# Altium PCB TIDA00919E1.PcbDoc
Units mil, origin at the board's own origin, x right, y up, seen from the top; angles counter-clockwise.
Board outline 2372.12 x 2864.32 mil, 2 copper layers (Top Layer, Bottom Layer), stack 62 mil thick; 37 components, 22 nets, 86 pads, 4 vias.
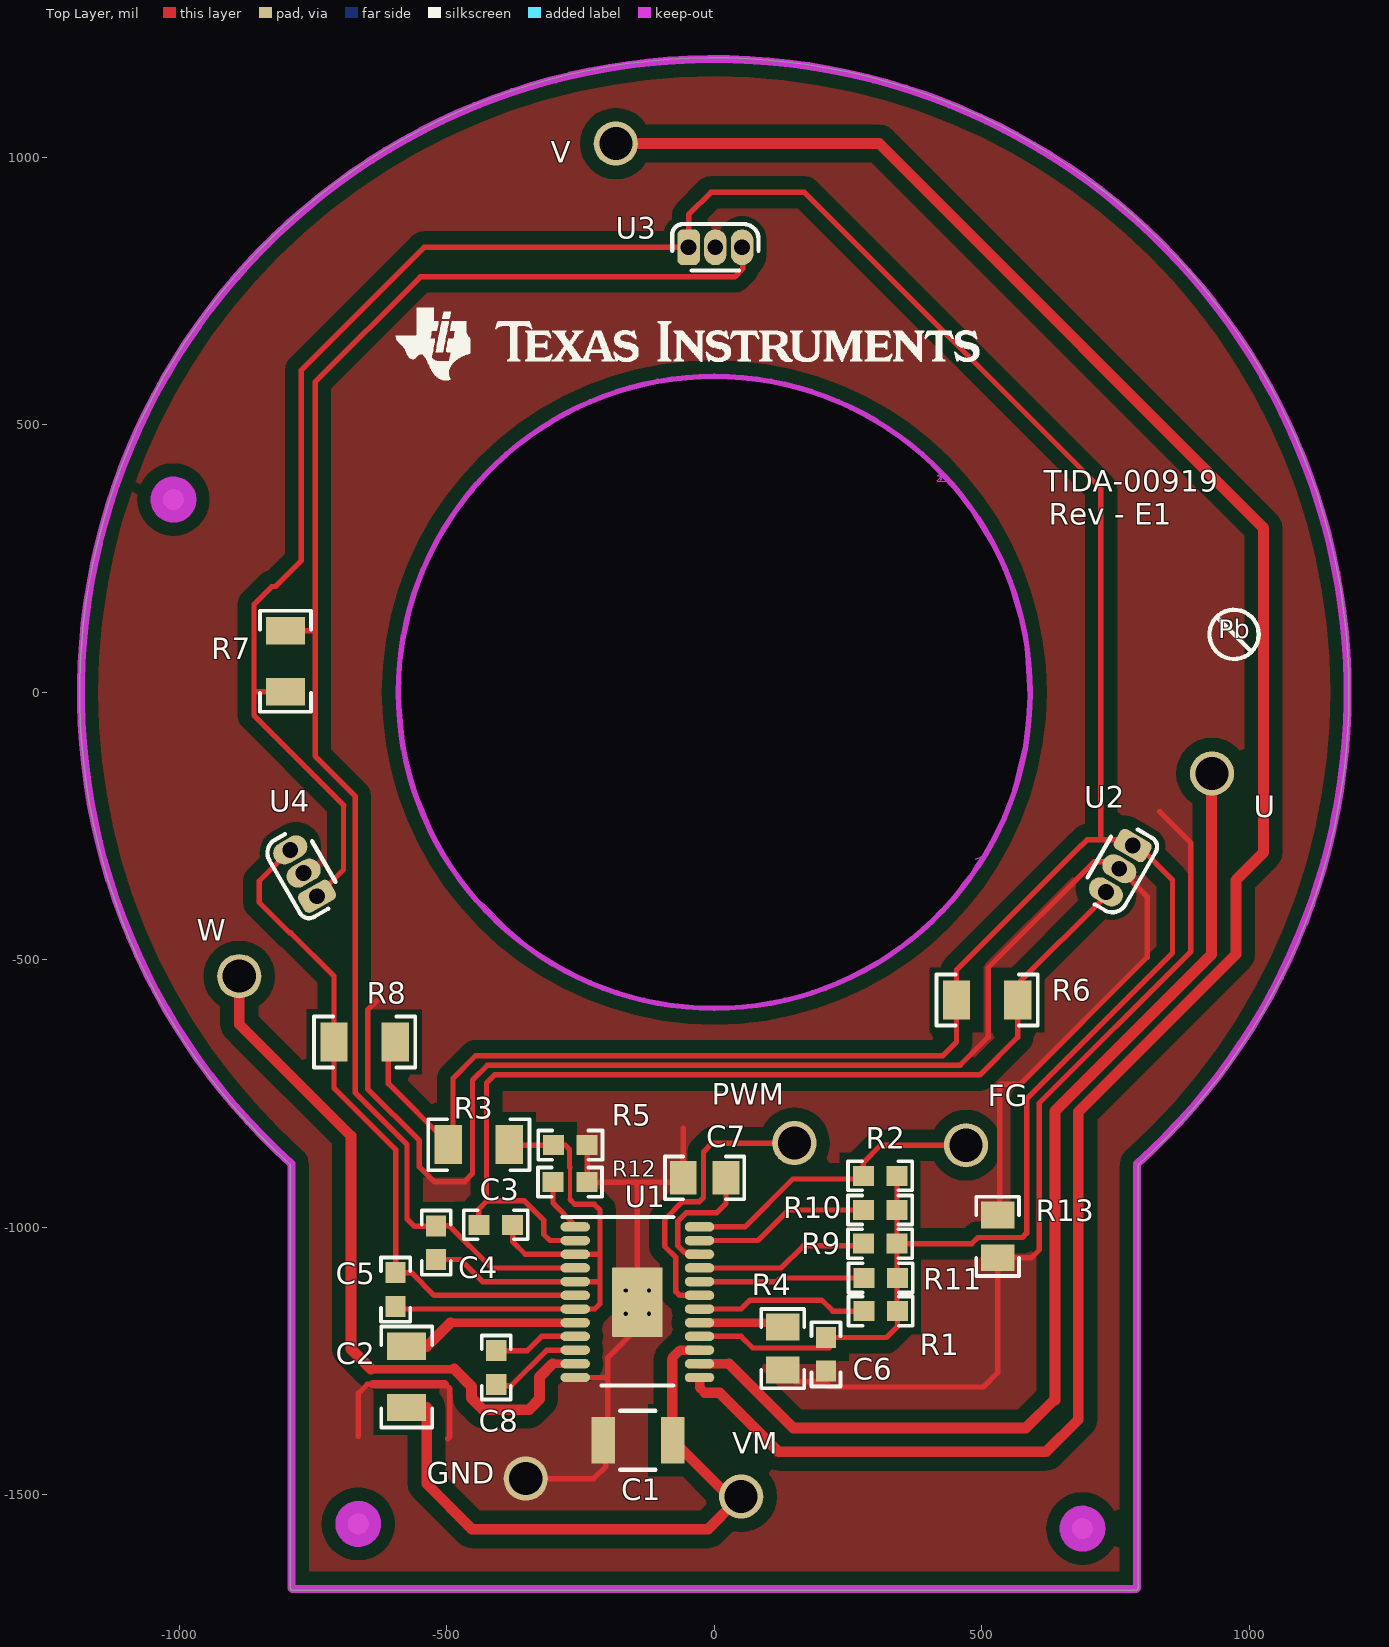
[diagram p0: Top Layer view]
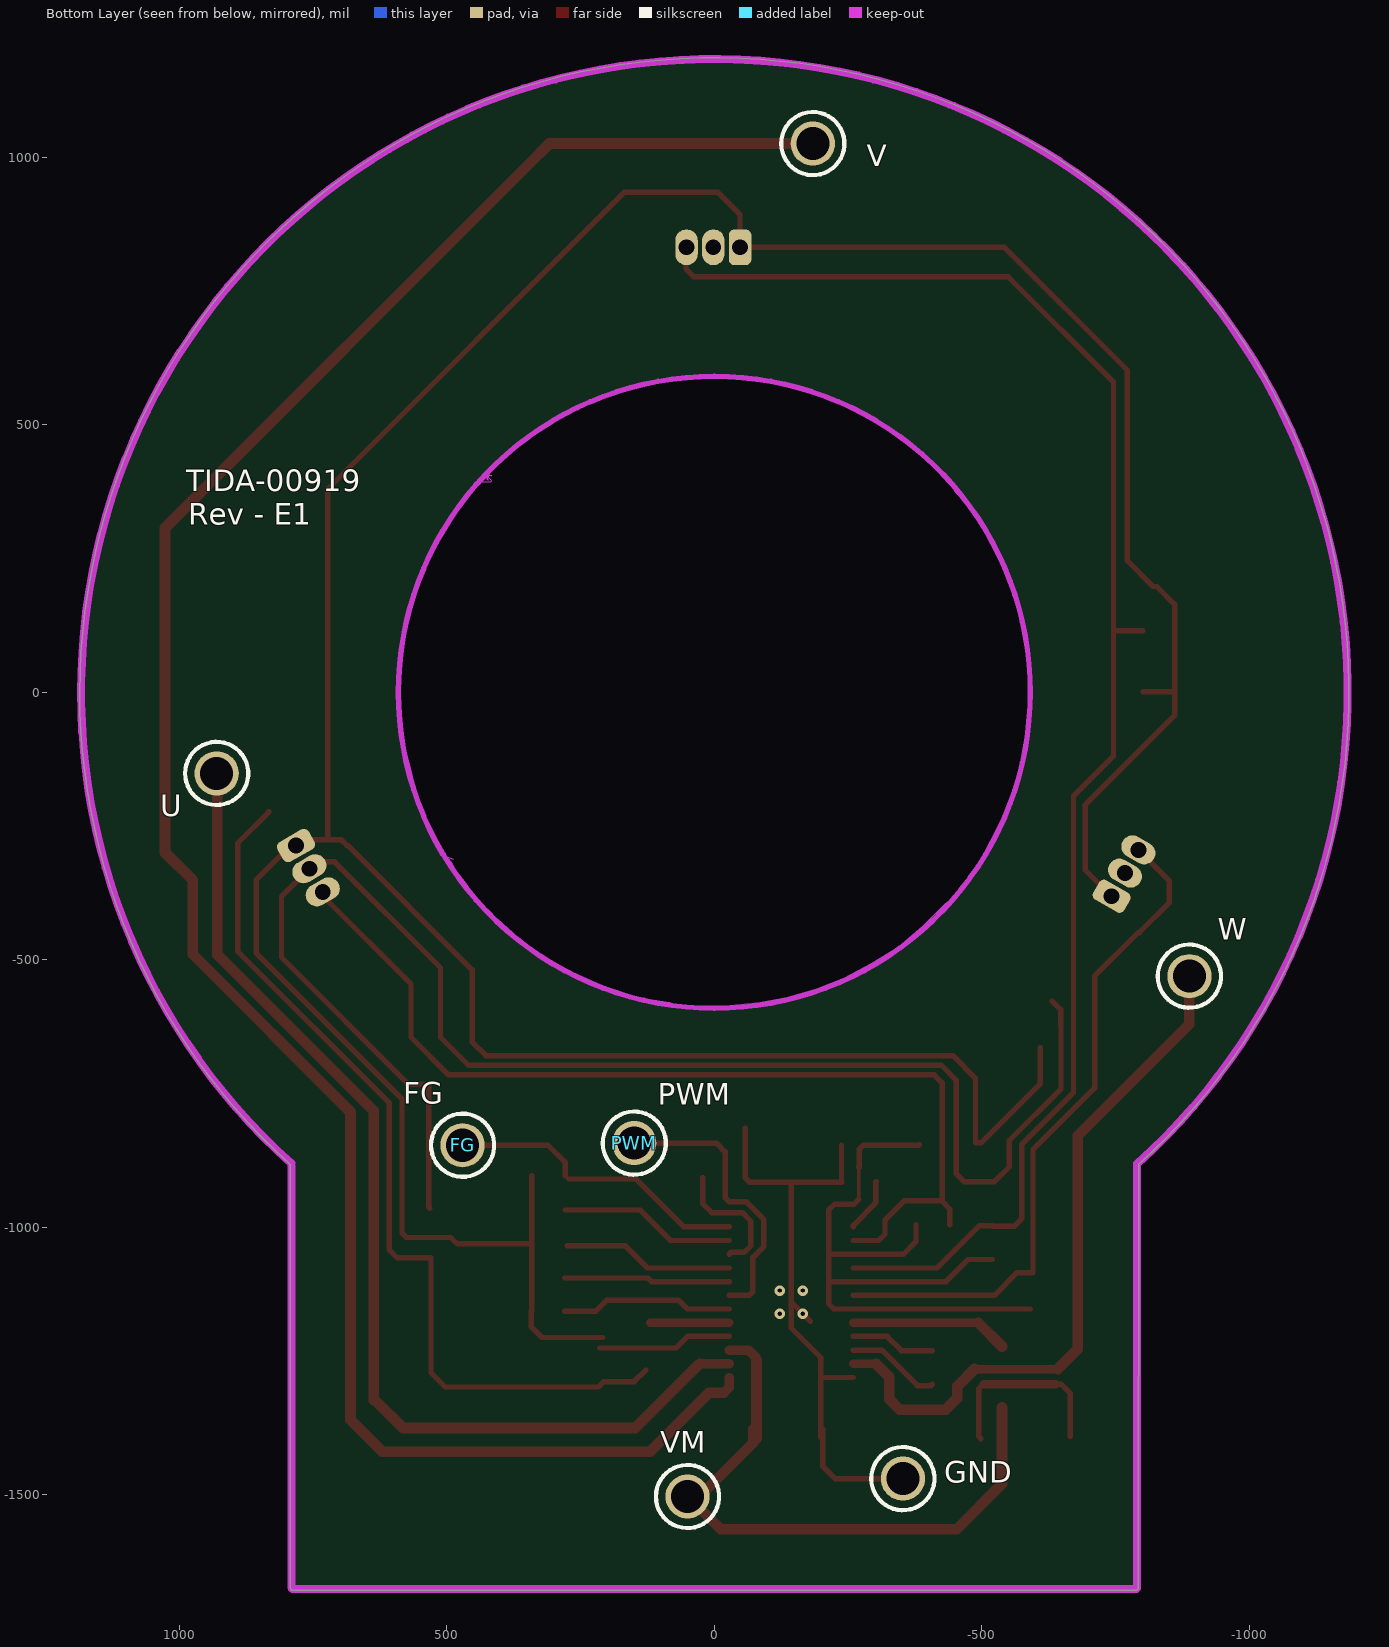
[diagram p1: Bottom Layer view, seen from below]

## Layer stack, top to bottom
Top Solder: solder mask 0.4, Solder Resist, Dk 3.5
Top Layer: signal copper 1.4
Dielectric1: core 59.2, FR-4, Dk 4.8
Bottom Layer: signal copper 1.4
Bottom Solder: solder mask 0.4, Solder Resist, Dk 3.5

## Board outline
-787.4,-1678.24 cw(c-787.4,-1673.23) -792.42,-1673.2 -792.7,-882.32 cw(c0,0) 1186.12,0 cw(c0,0) 793.67,-881.46 cw(c790.31,-877.73) 792.63,-882.18 792.42,-1673.23 ccw(c787.4,-1673.23) 792.42,-1673.23 cw(c787.4,-1673.23) 787.4,-1678.24
cut-out: 416.34,404.53 424.78,404.53 434.11,395.2 434.11,394.01 418,394.01 416.34,395.67 421.85,401.18 421.85,407.51
cut-out: -436.62,396.36 -451.1,373.34 -471.25,353.19 -487.33,327.93 -515.88,280.69 -544.87,227.97 -562.01,174.21 -573.92,119.3 -585.87,64.24 -588.58,3.94 -576.47,-123.77 -556.28,-188.69 -515.88,-285.26 -475.52,-345.3 -446.62,-383.83 -430.29,-396.48 -388.44,-438.33 -344.12,-476.69 -293.44,-507.7 -243.11,-533.99 -216.54,-544.29 -190.12,-554.53 -135.73,-570.87 -84.65,-580.39 -19.68,-586.61 38.39,-585.63 70.87,-583.49 83.36,-580.39 120.14,-574.76 153.68,-566.74 209.65,-548.23 273.62,-519.68 361.21,-467.56 432.76,-397.77 442.13,-388.63 466.41,-354.15 480.78,-336.32 488.06,-323.4 489.12,-321.52 499.74,-307.53 488.06,-311.83 499.06,-307.78 505.04,-299.29 518.37,-280.36 536.89,-236.79 555.12,-193.9 566.82,-146.01 578.2,-99.41 584.34,-51.58 586.61,-6.89 584.34,43.1 581.72,71.85 578.2,110.39 566.93,148.54 546.54,217.6 528.08,259.19 475.71,344.99 443.19,385.34 425.03,402.67 423.4,401.84 424.08,397 423.28,401.78 426.46,402.85 422.3,396.62 423.28,397.64 423.28,398.62 424.08,397.64 425.53,402.45 418.18,412.58 384.15,443.65 372.9,454.9 312.86,497.22 282.5,516.14 240.09,537.61 173.1,562.66 92.39,580.88 8.73,587.77 -55.02,587.77 -118.73,574.49 -135.73,570.94 -168.63,562.66 -208.15,549.34 -228.36,541.57 -252.1,529.7 -267.68,522.52 -282.61,513.96 -307.48,499.69 -328.87,486.4 -381.51,448.11 -434.84,395.94

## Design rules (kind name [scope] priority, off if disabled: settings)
AcuteAngle [All] p1: minimum=4.50000000000000E+0001 checktracksonly=FALSE
AssemblyTestPointUsage [All] p1: valid=2
Clearance Clearance_Keepouts [((IsTrack Or IsArc) And Not InPoly) And IsFree and IsKeepOut vs ((IsTrack Or IsArc) And Not InPoly) And IsFree and IsKeepOut] p1: gap=0
Clearance Clearance_BoardEdge_MountingHoles [OnCopper and InComponentClass('Mounting Holes') vs IsKeepOut] p2: gap=40
Clearance Clearance_BoardEdge_Poly [OnCopper and InPoly vs IsKeepOut] p3: gap=25
Clearance Clearance_BoardEdge [OnCopper and Not InComponentClass('Logo') and not InComponentClass('FiducialMark') and not InRegion(1000,500,4000,800) and Not IsKeepout vs IsKeepOut] p4: gap=75
Clearance Clearance_Poly [InPolygon] p5: gap=25
Clearance [All] p6: gap=7.87
ComponentClearance ComponentClearance_MountingHoles_FiducialMarks [InComponentClass('Mounting Holes') vs InComponentClass('FiducialMark')] p1: gap=50 collisioncheckmode=3 verticalgap=10 showdistances=FALSE
ComponentClearance ComponentClearance_Shunt [InComponentClass('Header') vs InComponentClass('Shunt')] p2: gap=0 collisioncheckmode=3 verticalgap=0 showdistances=FALSE
ComponentClearance ComponentClearance_Logo [InComponentClass('Logo')] p3: gap=50 collisioncheckmode=3 verticalgap=10 showdistances=FALSE
ComponentClearance ComponentClearance_ScrewToNut [(HasFootprint('NY PMS 440 0025 PH')) vs (HasFootprint('Keystone_1902C'))] p4: gap=5 collisioncheckmode=3 verticalgap=10 showdistances=FALSE
ComponentClearance ComponentClearance_MountingHoles [InComponentClass('Mounting Holes')] p5: gap=250 collisioncheckmode=3 verticalgap=100000 showdistances=FALSE
ComponentClearance ComponentClearance_SmallPassives [HasFootprint('0201*') or HasFootprint('0402*') or HasFootprint('0508') or HasFootprint('0603*') or HasFootprint('0612') or HasFootprint('0805*') or HasFootprint('0815*') or HasFootprint('0830*') or HasFootprint('1206*') or HasFootprint('1210*') or HasFootprint('1808*') or HasFootprint('1812*') or HasFootprint('1825*') or HasFootprint('2010*') or HasFootprint('2220*') or HasFootprint('2225*') or HasFootprint('2512*') or HasFootprint('2728*') or HasFootprint('3518*') vs HasFootprint('0201*') or HasFootprint('0402*') or HasFootprint('0508') or HasFootprint('0603*') or HasFootprint('0612') or HasFootprint('0805*') or HasFootprint('0815*') or HasFootprint('0830*') or HasFootprint('1206*') or HasFootprint('1210*') or HasFootprint('1808*') or HasFootprint('1812*') or HasFootprint('1825*') or HasFootprint('2010*') or HasFootprint('2220*') or HasFootprint('2225*') or HasFootprint('2512*') or HasFootprint('2728*') or HasFootprint('3518*')] p6: gap=20 collisioncheckmode=3 verticalgap=10 showdistances=FALSE
ComponentClearance ComponentClearance_THtoSMT [IsThruComponent vs IsSMTComponent] p7: gap=100 collisioncheckmode=3 verticalgap=30 showdistances=FALSE
ComponentClearance ComponentClearance_THtoTH [IsThruComponent vs IsThruComponent] p8: gap=118.11 collisioncheckmode=3 verticalgap=30 showdistances=FALSE
ComponentClearance [All] p9: gap=40 collisioncheckmode=3 verticalgap=10 showdistances=FALSE
DiffPairsRouting [All] p1: maxlimit=100 minlimit=10 mostfreqgap=10 toplayer_minwidth=15 toplayer_maxwidth=15 toplayer_prefwidth=15 bottomlayer_minwidth=15 bottomlayer_maxwidth=15 bottomlayer_prefwidth=15 maxuncoupledlength=1000
FabricationTestPointUsage TestPointUsage [All] p1: valid=2 allowmultiple=FALSE
FabricationTestpoint Testpoint [All] p1: side=3 testpointundercomponent=TRUE minsize=40 maxsize=100 preferedsize=60 minholesize=0 maxholesize=40 preferedholesize=32 testpointgrid=1 allowsidetop=TRUE allowsidebottom=TRUE usegrid=TRUE gridtolerance=0.01
FanoutControl Fanout_LCC [IsLCC] p1: bgadir=Out bgaviamode=Centered fanoutstyle=Auto fanoutdirection=Alternating viagrid=1 // Fanout_LCC (Default Rule)
FanoutControl Fanout_BGA [IsBGA] p2: bgadir=Out bgaviamode=Centered fanoutstyle=Auto fanoutdirection=Alternating viagrid=1 // Fanout_BGA (Default Rule)
FanoutControl Fanout_Default [All] p4: bgadir=Out bgaviamode=Centered fanoutstyle=Auto fanoutdirection=Alternating viagrid=1 // Fanout_Default (Default Rule)
FanoutControl Fanout_Small [(CompPinCount < 5)] p5: bgadir=Out bgaviamode=Centered fanoutstyle=Auto fanoutdirection=OutThenIn viagrid=1 // Fanout_Small (Default Rule)
HoleSize [All] p1: absolutevalues=TRUE maxlimit=251 minlimit=7 maxpercent=80.000 minpercent=20.000
MinimumAnnularRing MinimumAnnularRing_ThermalPadVias [IsVia and InAnyComponent] p1: minimumring=5.91
MinimumAnnularRing [All] p2: minimumring=5
MinimumSolderMaskSliver MinimumSolderMaskSliver_Logo [InComponentClass('Logo') vs InComponentClass('Logo')] p1: minsoldermaskwidth=0.7
MinimumSolderMaskSliver [All] p2: minsoldermaskwidth=3.93
PlaneConnect [All] p1: planeconnectstyle=Relief reliefexpansion=10 reliefentries=4 reliefconductorwidth=10 reliefairgap=10
PolygonConnect [All] p1: connectstyle=Direct reliefconductorwidth=10 reliefentries=4 polygonreliefangle="90 Angle" airgapwidth=10
RoutingVias ThermalPadVias [IsVia and InAnyComponent] p1: holewidth=7.87 width=19.68 viastyle="Through Hole" minholewidth=7.87 minwidth=19.68 maxholewidth=12.99 maxwidth=23.62
RoutingVias [All] p2: holewidth=16 width=34 viastyle="Through Hole" minholewidth=7.87 minwidth=26 maxholewidth=40 maxwidth=65
SilkToBoardRegionClearance [Not ((IsComment or IsDesignator) And (Hide <> 'False')) and not InRegion(1000,500,4000,800)] p1:
SilkToSilkClearance SilkToSilkClearance_Pb-FreeLogo [(HasFootprint('Pb-Free_Overlay_Medium') OR HasFootprint('Pb-Free_Overlay_Small')) vs (HasFootprint('Pb-Free_Overlay_Medium') OR HasFootprint('Pb-Free_Overlay_Small'))] p1: silktosilkclearance=0
SilkToSilkClearance [All] p2: silktosilkclearance=4
SilkToSolderMaskClearance SilkToComonentPadClearance [IsPad and InAnycomponent] p1: minsilkscreentomaskgap=5 clearancetoexposedcopper=TRUE
SilkToSolderMaskClearance "Silk to Solder Mask Opening" [All] p2: minsilkscreentomaskgap=4 clearancetoexposedcopper=FALSE
SolderMaskExpansion [All] p1: expansion=1.97
Width [All] p1: maxlimit=100 minlimit=6 preferedwidth=10 checkconnectedcopper=TRUE
15 further rules are at their usual default settings.

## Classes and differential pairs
component class TIDA_00919: C1 C2 C3 C4 C5 C6 C7 C8 FG GND PWM R1 R2 R3 R4 R5 R6 R7 R8 R9 R10 R11 R12 R13 U U1 U2 U3 U4 V VM W
component class TID_Hardware: Logo2

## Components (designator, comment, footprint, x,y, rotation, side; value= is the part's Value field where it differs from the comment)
1 "Fiducial" Fiducial10-20 687.99,-1562.99 r0 top
2 "Fiducial" Fiducial10-20 -665.35,-1554.13 r0 top
3 "Fiducial" Fiducial10-20 -1010.83,360.24 r0 top
4 "Texas Instruments" TI_Horizontal_Overlay_Small -50.2,651.57 r0 top
5 "Pb-Free Symbol" Pb-Free_Overlay_Small 971.46,108.27 r0 top
C1 "C3225X7R1H106M250AC" 1210_280 -142.72,-1397.64 r180 top
C2 "C3216X7R1E105K085AA" 1206 -574.8,-1279.53 r270 top
C3 "C0603C104M4RACTU" 0603 -408.46,-995.08 r180 top
C4 "C0603C104M4RACTU" 0603 -519.68,-1028.54 r90 top
C5 "C0603C104M4RACTU" 0603 -595.47,-1116.14 r90 top
C6 "C0603C225K8PACTU" 0603 208.66,-1237.2 r270 top
C7 "CC0805KRX7R8BB104" 0805_HV -18.07,-907.48 r180 top
C8 "06033C104KAT2A" 0603 -407.48,-1261.81 r270 top
FG "TESTPOINT" Keystone_1402-3 470.47,-846.46 r90 bottom
GND "TESTPOINT" Keystone_1402-3 -352.36,-1469.49 r180 bottom
PWM "TESTPOINT" Keystone_1402-3 149.65,-842.48 r90 bottom
R1 "CRCW060310K0JNEA" 0603 311,-1156.52 r0 top
R2 "CRCW060310K0JNEA" 0603 310.04,-903.52 r0 top
R3 "CRCW120610K0JNEA" 1206 -439.96,-845.47 r180 top
R4 "RT0805BRD0724KL" 0805_HV 127.95,-1226.38 r90 top
R5 "CRCW060310K0JNEA" 0603 -268.99,-846.16 r180 top
R6 "CRCW120610K0JNEA" 1206 509.84,-574.8 r180 top
R7 "CRCW120610K0JNEA" 1206 -801.18,58.07 r270 top
R8 "CRCW120610K0JNEA" 1206 -653.54,-653.54 r0 top
R9 "CRCW060310K0JNEA" 0603 310.04,-1030.51 r0 top
R10 "CRCW060310K0JNEA" 0603 310.04,-967.5 r0 top
R11 "CRCW060310K0JNEA" 0603 311.02,-1094.49 r0 top
R12 "CRCW060310K0JNEA" 0603 -269.69,-915.35 r180 top
R13 "CRCW08050000Z0EA" 0805_HV 529.53,-1016.73 r270 top
U "TESTPOINT" Keystone_1402-3 930.12,-151.57 r180 bottom
U1 "DRV10970PWP" PWP0024D_N -143.7,-1139.76 r0 top
U2 "DRV5013ADQLPGM" LPG0003A 756.89,-329.72 r240 top
U3 "DRV5013ADQLPGM" LPG0003A 1.97,831.69 r0 top
U4 "DRV5013ADQLPGM" LPG0003A -767.46,-337.9 r120 top
V "TESTPOINT" Keystone_1402-3 -184.06,1025.59 r180 bottom
VM "TESTPOINT" Keystone_1402-3 50.2,-1502.95 r180 bottom
W "TESTPOINT" Keystone_1402-3 -887.8,-530.51 r180 bottom

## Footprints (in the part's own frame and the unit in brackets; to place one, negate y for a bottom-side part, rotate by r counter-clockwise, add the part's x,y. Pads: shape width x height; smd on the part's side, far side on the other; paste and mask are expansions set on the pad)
0603 [mm] "0603 from SM-752 data"
  rect 1x0.95 smd: 1(-0.8,0) 2(0.8,0)
  silkscreen extent -1.52,-0.69 1.52,0.69, body extent -0.87,-0.47 0.87,0.47, height 1
0805_HV [mil] "0805 with 30mil clearance between pads"
  rect 50x63 smd: 1(-40,0) 2(40,0)
  silkscreen extent -74,-40 74,40, body extent -43,-29 43,29, height 57
1206 [mm] "1206 from SM-752 data"
  rect 1.3x1.85 smd: 1(-1.45,0) 2(1.45,0)
  silkscreen extent -2.4,-1.21 2.4,1.21, body extent -1.7,-0.9 1.7,0.9, height 1.35
1210_280 [mm] "SMD, 2-Leads, Body 3.6x2.8mm, Height 2.8mm"
  rect 1.1x2.2 smd: 1(-1.65,0) 2(1.65,0)
  silkscreen extent -0.84,-1.4 0.84,1.4, body extent -1.8,-1.4 1.8,1.4, height 2.8
Fiducial10-20 [mm]
  round 1 smd mask+0.5: 1(0,0)
  Top Layer keep-out circle w1.178: c0,0 r0.5
Keystone_1402-3 [mm] "Micro Pin, Swage Mount"
  round 2.1 hole 1.57: 1(0,0)
  silkscreen extent -1.5,-1.5 1.5,1.5, body extent -1.18,-1.18 1.18,1.18, height 7.01
LPG0003A [mm] "TO, Flat Index; 3 In-Line, Axial Leads Texas Instruments Recommended"
  rrect50% 1.07x1.7 hole 0.75: 1(-1.27,0)
  oval 1.07x1.7 hole 0.75: 2(0,0) 3(1.27,0)
  silkscreen extent -2.05,-1.1 2.05,1.1, body extent -2,-0.98 2,0.54, height 5.06
Pb-Free_Overlay_Small [mil]
  silkscreen extent -46,-46 46,46
PWP0024D_N [mm] "SOP, 24-Leads, Body 7.8x4.4mm, Pitch 0.65mm, Thermal Pad 3.3X2.4mm, IPC Medium Density"
  rrect100% 1.4x0.45 smd: 1(-2.95,3.575) 2(-2.95,2.925) 3(-2.95,2.275) 4(-2.95,1.625) 5(-2.95,0.975) 6(-2.95,0.325) 7(-2.95,-0.325) 8(-2.95,-0.975) 9(-2.95,-1.625) 10(-2.95,-2.275) 11(-2.95,-2.925) 12(-2.95,-3.575) 13(2.95,-3.575) 14(2.95,-2.925) 15(2.95,-2.275) 16(2.95,-1.625) 17(2.95,-0.975) 18(2.95,-0.325) 19(2.95,0.325) 20(2.95,0.975) 21(2.95,1.625) 22(2.95,2.275) 23(2.95,2.925) 24(2.95,3.575)
  rrect4% 2.4x3.3 smd: 25(0,0)
  silkscreen extent -3.55,-3.95 1.7,4.05, body extent -3.21,-3.9 3.21,3.9, height 1.2
TI_Horizontal_Overlay_Small [mil]
  silkscreen extent -545,-68 545,67

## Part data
1 2 3: "Fiducial mark.  There is nothing to buy or mount."
4: library part TI_Logo, "Texas Instrument Corporate Signature"
5: library part Pb-Free
C1: "CAP, CERM, 10 µF, 50 V, +/- 20%, X7R, 1210"
C2: "CAP, CERM, 1 µF, 25 V, +/- 10%, X7R, 1206"
C3 C4 C5: "CAP, CERM, 0.1 µF, 16 V, +/- 20%, X7R, 0603"
C6: "CAP, CERM, 2.2 µF, 10 V, +/- 10%, X5R, 0603"
C7: "CAP, CERM, 0.1 µF, 25 V, +/- 10%, X7R, 0805"
C8: "CAP, CERM, 0.1 µF, 25 V, +/- 10%, X7R, 0603"
FG GND PWM U V VM W: library part 1402-3, "Micro Pin, Gold, Swage Mount"
R1 R2 R5 R9 R10 R11 R12: "RES, 10 k, 5%, 0.1 W, 0603"
R3 R6 R7 R8: "RES, 10 k, 5%, 0.25 W, 1206"
R4: "RES, 24.0 k, 0.1%, 0.125 W, 0805"
R13: "RES, 0, 5%, 0.125 W, 0805"
U1: "3-Phase Brushless DC Motor Driver, PWP0024D"
U2 U3 U4: "Digital-Latch Hall Effect Sensor, LPG0003A"

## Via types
v1: diameter 19.68, hole 7.87, Top Layer to Bottom Layer, 4 vias

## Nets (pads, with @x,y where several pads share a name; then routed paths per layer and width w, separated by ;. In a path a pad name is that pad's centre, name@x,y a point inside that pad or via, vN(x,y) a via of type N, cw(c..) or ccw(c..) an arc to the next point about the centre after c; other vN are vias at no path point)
BRKMOD: R9.1 U1.21 | length 319.3
  Top Layer w10: U1.21 125,-1075.79 166.34,-1034.45 R9.1@274.61,-1034.45
CMTMOD: R11.1 U1.20 | length 309.9
  Top Layer w10: U1.20 117.13,-1101.38 124.02,-1094.49 R11.1
CPN: C8.2 U1.10 | length 176.2
  Top Layer w10: C8.2 -404.98,-1295.81 -379.47,-1295.81 -312.99,-1229.33 U1.10
CPP: C8.1 U1.9 | length 158.6
  Top Layer w10: C8.1 -349.41,-1230.31 -322.83,-1203.74 U1.9
CS: R4.2 U1.17 | length 147.3
  Top Layer w16: U1.17 R4.2@119.72,-1178.15
DAA: R12.2 U1.1 | length 102.3
  Top Layer w10: R12.2@-302.46,-914.37 -301.47,-915.35 -301.47,-954.43 -259.84,-996.06 U1.1
FG: FG.1 R2.1 U1.24 | length 567.2
  Top Layer w10: U1.24 57.09,-999.02 146.65,-909.45 R2.1@272.62,-909.45 ; R2.1 278.54,-878.94 311.02,-846.46 FG.1
FR: R10.1 U1.23 | length 329.8
  Top Layer w10: U1.23 81.69,-1024.61 138.8,-967.5 R10.1
GND: C1.2 C6.2 C7.2 GND.1 R4.1 R5.1 R12.1 R13.1 R13.2 U1.12 U1.25 U2.2 U3.2 U4.2 | length 6131.9
  Top Layer w10: -665.35,-1390.75 -665.35,-1310.04 -648.62,-1293.31 -637.8,-1293.31 ; -630.91,-576.77 -647.09,-592.95 -647.6,-592.95 -647.6,-621.44 -647.72,-621.56 -647.72,-741.06 -551.18,-837.6 -551.18,-886.81 -523.62,-914.37 -466.54,-914.37 -451.77,-899.61 -451.77,-724.57 -424.21,-697.01 459.49,-697.01 511.81,-644.69 511.81,-514.76 709.65,-316.93 744.09,-316.93 U2.2 809.06,-381.89 809.06,-495.08 571.38,-732.76 533.46,-732.76 533.46,-962.6 R13.1@531.5,-964.57 ; -503.94,-1293.31 -501.97,-1293.31 -494.09,-1301.18 -494.09,-1390.75 -498.03,-1394.68 ; GND.1 -225.39,-1469.49 -202.76,-1446.85 C1.2@-202.76,-1376.97 ; U1.12 -201.77,-1280.51 -198.82,-1277.56 ; R5.1 -237.5,-914.37 -238.48,-915.35 -145.67,-915.35 ; C1.2@-198.82,-1392.72 -198.82,-1277.56 ; U1.25@-179.13,-1175.2 U1.25 ; -58.07,-814.96 C7.2 -65.95,-915.35 -145.67,-915.35 ; R4.1 149.96,-1288.39 206.69,-1288.39 216.54,-1298.23 502.95,-1298.23 529.53,-1271.65 R13.2 592.87,-1056.73 607.28,-1042.32 607.28,-767.72 890.75,-484.25 890.75,-281.5 832.68,-223.43 ; -198.82,-1277.56 -198.82,-1243.11 -143.7,-1187.99 U1.25 ; -145.67,-915.35 -143.7,-917.32 U1.25
  Top Layer w16: -637.8,-1293.31 -503.94,-1293.31
  other v1: -165.35,-1161.42 -122.05,-1161.42 -165.35,-1118.11 -122.05,-1118.11
PWM: PWM.1 U1.19 | length 546.1
  Top Layer w10: U1.19 -64.96,-1126.97 -71.85,-1120.08 -71.85,-1056.1 -92.52,-1035.43 -92.52,-985.24 -59.14,-951.85 -27.74,-951.85 -20.2,-944.31 -20.2,-858.74 -3.94,-842.48 PWM.1 PWM.1@152.56,-839.57
RD: R1.1 U1.18 | length 322.6
  Top Layer w10: U1.18 50.2,-1152.56 66.93,-1135.83 200.79,-1135.83 221.48,-1156.52 R1.1
RETRY: C7.1 U1.22 | length 244.8
  Top Layer w10: U1.22 -31.42,-1046.34 -56.34,-1046.34 -67.99,-1034.68 -67.99,-988.2 -52.23,-972.44 4.92,-972.44 21.93,-955.43 C7.1
U: U1.14 U.1 | length 2028.5
  Top Layer w10: 634.23,-1322.81 636.81,-1322.81 ; U.1@929.13,-152.56 U.1
  Top Layer w17.72: U1.14 27.56,-1254.92
  Top Layer w20: 27.56,-1254.92 147.64,-1375 582.05,-1375 634.23,-1322.81 ; 636.81,-1322.81 636.81,-782.48 929.13,-490.16 U.1@929.13,-152.56
U_HN: C3.1 C4.1 C5.1 R3.1 R5.2 U1.3 U1.5 U1.7 | length 1359.7
  Top Layer w7: -269.69,-947.83 -269.69,-887.8
  Top Layer w10: C5.1@-590.55,-1152.56 U1.7 -223.43,-1152.56 -213.58,-1142.72 -213.58,-1099.41 ; C4.1 -474.41,-1060.04 -433.07,-1101.38 U1.5 -215.55,-1101.38 -213.58,-1099.41 ; R3.1 -382.18,-846.16 R5.2 -278.54,-846.16 -270.67,-854.04 -270.67,-887.8 -269.69,-887.8 ; C3.1 -376.97,-1026.57 -353.35,-1050.2 U1.3 -213.58,-1050.2 ; -269.69,-947.83 -260.83,-956.69 -224.41,-956.69 -213.58,-967.52 -213.58,-1050.2 ; -213.58,-1099.41 -213.58,-1050.2
U_HP: C3.2 R6.1 U1.2 U2.3 | length 1851.6
  Top Layer w10: C3.2 -439.96,-965.55 -425.2,-950.79 -425.69,-950.3 ; U1.2 -307.09,-1024.61 -318.9,-1012.8 -318.9,-986.22 -354.82,-950.3 -425.69,-950.3 ; U2.3 731.89,-380.32 566.93,-545.28 R6.1 566.93,-644.69 496.73,-714.88 -410.75,-714.88 -425.69,-729.82 -425.69,-950.3
V: U1.13 V.1 | length 4119.1
  Top Layer w17.72: U1.13 -27.56,-1299.21 -17.72,-1309.06
  Top Layer w20: V.1 308.07,1025.59 346.95,986.71 1026.57,307.09 1026.57,-299.21 974.85,-350.94 974.85,-489.72 680.12,-784.45 680.12,-1359.25 620.08,-1419.29 120.08,-1419.29 9.84,-1309.06 -17.72,-1309.06
V_HP: C4.2 R7.1 U1.4 U3.3 | length 2965.5
  Top Layer w10: R7.1 -749.02,115.16 ; U1.4 -415.84,-1075.79 -494.58,-997.05 C4.2 -520.67,-998.03 -560.2,-998.03 -574.31,-983.92 -574.31,-844.98 -671.19,-748.1 -671.19,-193.9 -746.06,-119.02 -746.06,579.72 -549.21,776.57 38.39,776.57 52.96,791.15 U3.3@52.96,829.72
VCP: C2.1 U1.8 | length 295.9
  Top Layer w16: -493.11,-1178.15 U1.8
  Top Layer w20: -537.4,-1222.44 -493.11,-1178.15
VINT: C6.1 R1.2 R2.2 R3.2 R6.2 R7.2 R8.2 R9.2 R10.2 R11.2 U1.16 U2.1 U3.1 U4.1 | length 7418.8
  Top Layer w10: R7.2 -859.25,0.98 -860.24,0 ; U4.1 -692.91,-331.65 -692.91,-212.6 -691.93,-211.61 -860.24,-43.31 -860.24,0 ; R8.2@-609.25,-664.37 -609.25,-731.3 -499.02,-841.54 -488.19,-841.54 -488.19,-721.46 -445.87,-679.13 427.17,-679.13 452.76,-653.54 R6.2 452.76,-518.7 685.03,-286.42 686.02,-286.42 696.85,-275.59 722.44,-275.59 ; U1.16 50.2,-1203.74 71.85,-1225.39 214.57,-1225.39 ; C6.1 321.85,-1205.71 342.5,-1185.06 R1.2 ; R1.2@341.54,-1156.5 R9.2 ; R2.2 R10.2 R9.2 ; -860.24,0 -860.24,164.37 -826.77,197.83 -819.88,197.83 -771.65,246.06 -771.65,602.36 -542.32,831.69 U3.1 -48.03,892.72 -6.44,934.31 168.64,934.31 722.44,380.51 722.44,-275.59 ; R9.2 481.04,-1030.51 492.7,-1018.86 575.63,-1018.86 583.66,-1010.83 583.66,-759.84 856.3,-487.2 856.3,-350.39 792.33,-286.42 U2.1 771.06,-275.59 722.44,-275.59
VM: C1.1 C2.2 U1.15 VM.1 | length 1172.1
  Top Layer w10: -78.74,-1248.03 -78.74,-1244.09 ; C1.1 C1.1@-72.83,-1402.56
  Top Layer w17.72: -78.74,-1244.09 -63.98,-1229.33 U1.15
  Top Layer w20: -537.4,-1336.61 -537.4,-1479.33 -452.76,-1563.98 -11.81,-1563.98 38.39,-1513.78 -72.83,-1402.56 C1.1@-72.83,-1376.97 ; C1.1@-78.74,-1394.68 -78.74,-1248.03
W: U1.11 W.1 | length 1327
  Top Layer w10: W.1@-917.32,-534.45 W.1@-914.37,-531.5 ; -683.07,-824.8 -679.13,-828.74 ; -641.73,-1264.76 -637.8,-1264.76 ; -503.94,-1264.76 -502.96,-1264.76 ; -492.13,-1264.76 -486.22,-1264.76
  Top Layer w16: -637.8,-1264.76 -503.94,-1264.76 -492.13,-1264.76 ; -302.17,-1254.92 U1.11
  Top Layer w20: W.1 -887.8,-620.08 -868.11,-639.76 -683.07,-824.8 ; -679.13,-828.74 -679.13,-1227.36 -641.73,-1264.76 ; -486.22,-1264.76 -453.74,-1297.24 -453.74,-1318.9 -432.09,-1340.55 -346.46,-1340.55 -326.77,-1320.87 -326.77,-1279.53 -302.17,-1254.92
W_HP: C5.2 R8.1 U1.6 U4.3 | length 1273.9
  Top Layer w10: U4.3 -850.39,-352.53 -850.39,-392.72 -793.8,-449.31 -791.83,-449.31 -710.63,-530.51 R8.1 -710.63,-739.62 -595.47,-854.78 C5.2 -565.94,-1084.65 -523.62,-1126.97 U1.6
pads on no net: 1.1 2.1 3.1

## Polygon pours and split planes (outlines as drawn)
GND on Top Layer "GND_L01_P010" (solid, remove dead copper, pour order 10): -1229.8,1260.3 -1225.86,1256.36 1257.41,1256.36 1257.41,-1792.85 -1243.58,-1792.85 -1243.58,1235.69 -1229.8,1249.47

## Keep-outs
Keep-Out Layer:
  circle w10: c0,0 r590.55
  lines w10: 787.4,-885.83 787.4,-1673.23 -787.4,-1673.23 -787.69,-880.08 cw(c0,0) 787.61,-880.15 ; -792.7,-882.32 cw(c0,0) 1186.12,0 ; -792.7,-882.32 cw(c0,0) 1186.12,0 ; -792.7,-882.32 -792.42,-1673.23 ; -792.7,-882.32 -792.42,-1673.23 ; -792.42,-1673.23 ccw(c-787.4,-1673.23) -787.4,-1678.24 ; -792.42,-1673.23 ccw(c-787.4,-1673.23) -787.4,-1678.24 ; -787.4,-1678.24 787.4,-1678.24 ; -787.4,-1678.24 787.4,-1678.24 ; 787.4,-1678.24 ccw(c787.4,-1673.23) 792.42,-1673.23 ; 787.4,-1678.24 ccw(c787.4,-1673.23) 792.42,-1673.23 ; 792.42,-1673.23 792.42,-885.83 792.42,-1673.23 ; 1186.12,0 cw(c0,0) 791.69,-883.23 ccw(c0,0) 1186.12,0 ; 3768.9,-1875.08 ccw(c3768.9,-1870.08) 3773.9,-1870.08 cw(c3768.9,-1870.08) 3768.9,-1875.08
  text ".Layer_Name" at -604.1,-2728.57 h60

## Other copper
Top Layer:
  text ".Layer_Name" at -604.1,-2728.57 h60
Bottom Layer:
  text ".Layer_Name" at -604.1,-2728.57 h60

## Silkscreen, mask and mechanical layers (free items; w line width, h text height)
Top Overlay:
  text "V" at -306.1,990.16 h40
  text "TIDA-00919" at 616.14,375 h40
  text "Rev - E1" at 625,312.99 h40
  text "U" at 1007.87,-233.27 h40
  text "W" at -967.52,-464.57 h40
  text "VM" at 33.46,-1423.23 h40
  text "GND" at -537.4,-1479.33 h40
  text ".Layer_Name" at -604.1,-2728.57 h60
Bottom Overlay:
  text "TIDA-00919" at 987.2,375.98 h40
  text "Rev - E1" at 983.27,312.99 h40
  text "FG" at 581.69,-768.7 h40
  text "PWM" at 105.32,-770.67 h40
  text ".Layer_Name" at -604.1,-2728.57 h60
Top Paste:
  text ".Layer_Name" at -604.1,-2728.57 h60
Bottom Paste:
  text ".Layer_Name" at -604.1,-2728.57 h60
Top Solder:
  text ".Layer_Name" at -604.1,-2728.57 h60
  text ".Layer_Name" at -604.1,-2728.57 h60
Bottom Solder:
  text ".Layer_Name" at -604.1,-2728.57 h60
Drill Guide:
  text ".Layer_Name" at -604.1,-2728.57 h60
M1 Board Outline:
  circle w10: c0,0 r590.55
  lines w10: 787.61,-880.15 787.4,-1673.23 -787.4,-1673.23 -787.69,-880.08 cw(c0,0) 790.31,-877.73
  text ".Layer_Name" at -604.1,-2728.57 h60
M2 Board Dimensions:
  rectangle: -1056.1,-2270.08 -681.1,-2145.08
  rectangle: -1181.1,-2145.08 -1056.1,-2020.08
  lines w7: -1181.1,-2145.08 -181.1,-2145.08 ; -1056.1,-2270.08 -1056.1,-2020.08 ; -931.1,-2270.08 -931.1,-2020.08 ; -681.1,-2270.08 -681.1,-2020.08 ; -431.1,-2270.08 -431.1,-2020.08 ; -1181.1,-2270.08 -1181.1,-2020.08 -181.1,-2020.08 -181.1,-2270.08 -1181.1,-2270.08
  text ".Layer_Name" at -604.1,-2728.57 h60
M3 3D STEP Top:
  text ".Layer_Name" at -604.1,-2728.57 h60
M4 3D STEP Bottom:
  text ".Layer_Name" at -604.1,-2728.57 h60
M5 Assembly Top:
  lines w10: -1473.1,-2800.25 5126.9,-2800.25 ; -1473.1,-2596.91 5128.9,-2596.91 ; -1473.1,-2393.58 -1473.1,-3003.58 2531.9,-3003.58 5128.9,-3003.58 5128.9,-2393.58 -1472.6,-2393.58 -1472.6,-3003.58 102.9,-3003.58 ; 991.9,-3003.58 991.9,-2393.58 ; 2258.9,-2596.91 2258.9,-2393.58 ; 3098.9,-2596.91 3098.9,-2393.58 ; 3720.9,-3010.08 3720.9,-2807.25
  text "COMPONENTS MARKED 'DNP' SHOULD NOT BE POPULATED." at -27.6,-2188.58 h60
  text "ASSEMBLY VARIANT:" at -28.1,-2304.08 h60
  text ".VariantName" at 1007.9,-2304.08 h60
  text "PCB VIEWED FROM TOP SIDE" at -1409.6,-2525.75 h60
  text "BOARD #:" at 1066.9,-2525.75 h60
  text ".PRJ_Number" at 1612.4,-2525.75 h60
  text "REV:" at 2456.9,-2525.75 h60
  text ".PCB_Rev" at 2748.4,-2525.75 h60
  text "SVN REV:" at 3294.9,-2525.75 h60
  text ".VersionControl_RevNumber" at 3800.9,-2525.75 h60
  text "TID #:" at 1066.9,-2729.08 h60
  text ".TID" at 1612.4,-2729.08 h60
  text "PLOT NAME =" at -1409.6,-2934.41 h60
  text ".plot_File_Name" at -604.1,-2934.41 h60
  text "GENERATED    :" at 1068.9,-2934.41 h60
  text ".Print_Date" at 1938.4,-2934.41 h60
  text ".Print_Time" at 2667.4,-2934.41 h60
  text "TEXAS INSTRUMENTS" at 3931.9,-2934.41 h60
M6 Assembly Bottom:
  lines w10: -1473.6,-2597.41 5128.4,-2597.41 ; -1471.6,-2800.75 5128.4,-2800.75 ; -65.6,-3010.58 -65.6,-2807.75 ; 556.4,-2597.41 556.4,-2394.08 ; 1396.4,-2597.41 1396.4,-2394.08 ; 2663.4,-3004.08 2663.4,-2394.08 ; 3552.4,-3004.08 5127.9,-3004.08 5127.9,-2394.08 -1473.6,-2394.08 -1473.6,-3004.08 1123.4,-3004.08 5128.4,-3004.08 5128.4,-2394.08
  text "COMPONENTS MARKED 'DNP' SHOULD NOT BE POPULATED." at 4920.9,-2188.08 h60
  text ".VariantName" at 3876.9,-2304.08 h60
  text "ASSEMBLY VARIANT:" at 4915.9,-2304.08 h60
  text ".VersionControl_RevNumber" at -145.6,-2526.25 h60
  text "SVN REV:" at 360.4,-2526.25 h60
  text ".PCB_Rev" at 906.9,-2526.25 h60
  text "REV:" at 1198.4,-2526.25 h60
  text ".PRJ_Number" at 2042.9,-2526.25 h60
  text "BOARD #:" at 2588.4,-2526.25 h60
  text "PCB VIEWED FROM BOTTOM SIDE" at 5064.9,-2526.25 h60
  text ".TID" at 2042.9,-2729.58 h60
  text "TID #:" at 2588.4,-2729.58 h60
  text "TEXAS INSTRUMENTS" at -276.6,-2934.91 h60
  text ".Print_Time" at 987.9,-2934.91 h60
  text ".Print_Date" at 1716.9,-2934.91 h60
  text "GENERATED    :" at 2586.4,-2934.91 h60
  text ".plot_File_Name" at 4259.4,-2934.91 h60
  text "PLOT NAME =" at 5064.9,-2934.91 h60
M9 Title Sheet:
  drawing of 57 lines, arcs and shapes, not listed
  text "1" at -441.27,6166.42 h70
  text "2" at 2054.4,6166.42 h70
  text "3" at 4543.74,6166.42 h70
  text "4" at 7050.41,6166.42 h70
  text "5" at 9549.4,6166.42 h70
  text "6" at 12054.4,6166.42 h70
  text "A" at -1597.6,5023.42 h70
  text "A" at 13202.4,5023.42 h70
  text "B" at -1597.6,2643.42 h70
  text "B" at 13202.4,2643.42 h70
  text "C" at -1597.6,268.42 h70
  text "C" at 13202.4,268.42 h70
  text "PROJECT TITLE:" at 10162.4,-1592.58 h45
  text ".PRJ_Title" at 10212.4,-1725.91 h70
  text "DESIGNED FOR:" at 10162.4,-1893.58 h45
  text ".PRJ_Customer" at 10212.4,-2033.58 h70
  text "D" at -1597.6,-2101.58 h70
  text "D" at 13202.4,-2101.58 h70
  text "FILE NAME:" at 10162.4,-2193.58 h45
  text ".PCB_File_Name_No_Path" at 10212.4,-2313.58 h70
  text "Texas Instruments (TI) and/or its licensors do not warrant the accuracy or completeness of this specification" at 5192.9,-2475.42 h45
  text "ENGINEER:" at 10162.4,-2483.58 h45
  text "LAYOUT BY:" at 11667.4,-2483.58 h45
  text "or any information contained therein. TI and/or its licensors do not warrant that this design will meet" at 5147.91,-2588.08 h45
  text ".PRJ_Engineer" at 10212.4,-2638.57 h70
  text ".PCB_Layout" at 11717.9,-2638.57 h70
  text "the specifications, will be suitable for your application or fit for any particular purpose, or will operate in" at 5147.91,-2700.75 h45
  text ".Layer_Name" at -604.1,-2728.57 h60
  text "ALTIUM DESIGNER VERSION:" at 11667.4,-2793.58 h45
  text "an implementation. TI and/or its licensors do not warrant that the design is production worthy. You should" at 5147.91,-2813.41 h45
  text "completely validate and test your design implementation to confirm the system functionality for your application." at 5192.9,-2926.08 h45
  text ".print_Scale" at 10212.4,-2926.91 h70
  text ".Application_BuildNumber" at 11717.9,-2926.91 h70
  text "1" at -441.27,-3133.58 h70
  text "2" at 2054.4,-3133.58 h70
  text "3" at 4543.74,-3133.58 h70
  text "4" at 7050.41,-3133.58 h70
  text "5" at 9549.4,-3133.58 h70
  text "6" at 12054.4,-3133.58 h70
M10 Fab Notes:
  drawing of 173 lines, arcs and shapes, not listed
  text "DESIGN INFORMATION" at 11195.92,4330.92 h60
  text "MIN. TRACK WIDTH:" at 10551.36,4150.92 h60
  text "8" at 11647.6,4150.92 h60
  text "MIL" at 11802.36,4150.92 h60
  text "MIN. CLEARANCE:" at 10551.36,4018.92 h60
  text "0.2" at 11587.6,4018.92 h60
  text "mm" at 11802.36,4018.92 h60
  text "MIN. VIA PAD SIZE:" at 10551.36,3886.92 h60
  text "24" at 11617.61,3886.92 h60
  text "MIL" at 11802.36,3886.92 h60
  text "0.05mm (2MIL)" at 11246.36,3745.21 h60
  text "MINIMUM ANNULAR RING" at 10222.13,3740.93 h60
  text "EXTERNAL" at 11954.36,3740.93 h60
  text "PER" at 10422.13,3622.92 h60
  text "IPC-D-275 CLASS 2 LEVEL C" at 10642.13,3622.92 h60
  text "MIL, HOLES" at 12130.36,3510.63 h60
  text "+/-" at 11737.9,3509.92 h60
  text "+/-" at 12591.9,3509.92 h60
  text "REGISTRATION TOLERANCES:" at 10222.13,3504.92 h60
  text "METAL" at 11421.9,3504.92 h60
  text "5" at 11998.1,3504.92 h60
  text "3" at 12831.1,3504.92 h60
  text "MIL" at 12947.36,3504.92 h60
  text "+/-" at 12591.9,3391.92 h60
  text "HOLE SIZE TOLERANCE (UNLESS OTHERWISE SPECIFIED):" at 10222.13,3386.92 h60
  text "3" at 12831.1,3386.92 h60
  text "MIL" at 12947.36,3386.92 h60
  text "MATERIAL:" at 10147.36,3177.46 h60
  text "FR-4 High Tg" at 11133.8,3037.13 h60
  text "FR-408" at 10568.36,3028.56 h60
  text "OTHER" at 12056.36,3028.56 h60
  text "X" at 10978.9,3024.92 h60
  text "62 MIL (1.6mm) +/-10%" at 10888.46,2865.84 h60
  text "THICKNESS:" at 10222.13,2861.56 h60
  text "X" at 10760.29,2861.56 h60
  text "OTHER" at 12173.36,2861.56 h60
  text "TOLERANCE:" at 10222.13,2703.56 h60
  text "X" at 11061.43,2703.56 h60
  text "ANSI IPC-6012 TYPE 3 CLASS 2" at 11248.37,2703.56 h60
  text "OTHER +/-" at 11248.36,2547.56 h60
  text "BOW & TWIST:" at 10222.13,2390.56 h60
  text "X" at 11061.43,2390.56 h60
  text "ANSI IPC-6012 TYPE 3 CLASS 2" at 11248.37,2390.56 h60
  text "OTHER +/-" at 11248.36,2232.05 h60
  text "DRILLING:" at 10147.36,2093.56 h60
  text "REFERENCE:" at 10222.13,1976.56 h60
  text "X" at 10870.36,1976.56 h60
  text "AS SHOWN" at 11057.36,1976.56 h60
  text "X" at 11771.36,1976.56 h60
  text "NC_DRILL FILES" at 11908.36,1976.56 h60
  text "PTH MIN COPPER THICKNESS:" at 10222.13,1818.56 h60
  text "X" at 11572.36,1818.56 h60
  text "1MIL" at 11709.36,1818.56 h60
  text "OTHER" at 12206.36,1818.56 h60
  text "BOARD FINISH:" at 10147.36,1659.56 h60
  text "SILKSCREEN:" at 10302.58,1541.56 h60
  text "X" at 11251.36,1541.56 h60
  text "TOP" at 11377.36,1541.56 h60
  text "X" at 11761.36,1541.56 h60
  text "BOTTOM" at 11888.36,1541.56 h60
  text "SILKSCREEN COLOR:" at 10302.58,1374.56 h60
  text "X" at 11250.32,1374.56 h60
  text "WHITE" at 11377.36,1374.56 h60
  text "OTHER" at 11888.36,1374.56 h60
  text "X" at 11381.32,1215.36 h60
  text "GREEN" at 11508.36,1215.36 h60
  text "OTHER" at 12126.36,1215.36 h60
  text "SOLDER RESIST COLOR:" at 10302.58,1204.56 h60
  text "X" at 11381.32,1045.36 h60
  text "MATTE" at 11508.36,1045.36 h60
  text "SEMI-GLOSS" at 12125.9,1044.73 h60
  text "IMMERSION GOLD (ENIG)" at 11208.36,856.84 h60
  text "ENEPIG" at 12545.9,853.56 h60
  text "SURFACE FINISH:" at 10147.36,852.56 h60
  text "X" at 11021.41,852.56 h60
  text "IMM. TIN/SILVER OR EQUIV" at 10476.9,695.56 h60
  text "OTHER" at 11908.36,695.56 h60
  text "ARRAY/PANEL:" at 10147.36,516.56 h60
  text "CUT AND TRIM PER M1 BOARD OUTLINE" at 11208.36,512.27 h60
  text "N.C. ROUTE" at 11208.36,360.56 h60
  text "X" at 11887.36,360.56 h60
  text "V. SCORE" at 12074.36,360.56 h60
  text "CERTIFICATION:" at 10147.36,223.56 h60
  text "MATERIALS AND WORKMANSHIP FOR ALL PCBS" at 10872.36,223.56 h60
  text "TO MEET OR EXCEED THE REQUIREMENTS OF:" at 10872.36,125.56 h60
  text "X" at 10498.86,-10.94 h60
  text "ANSI IPC-A-600F CLASS ->" at 10637.86,-10.94 h60
  text "X" at 12276.92,-10.94 h60
  text "2" at 12395.86,-10.94 h60
  text "1" at 12080.86,-12.44 h60
  text "3" at 12749.86,-12.44 h60
  text "X" at 11312.92,-170.44 h60
  text "RoHS" at 11449.86,-170.44 h60
  text "OTHER" at 12094.26,-170.44 h60
  text "PER ORDER" at 12491.32,-170.44 h60
  text "ALL BOARDS MUST MEET OR EXCEED UL94-V0 REQUIREMENTS." at 10174.9,-336.08 h60
  text "PCB MUST BEAR THE UL94V-0 UL REGISTERED MATERIAL ID NUMBER" at 10174.9,-456.08 h60
  text "ADDITIONAL REQUIREMENTS:" at 10147.36,-629.44 h60
  text "MICROSECTION:" at 10222.13,-744.44 h60
  text "YES" at 11127.86,-744.44 h60
  text "REQUIRED" at 11989.36,-900.58 h60
  text "BARE BOARD ELEC. TEST:" at 10222.13,-903.44 h60
  text "NONE" at 11527.86,-903.44 h60
  text "X" at 11862.36,-903.44 h60
  text "PER ORDER" at 12581.36,-903.44 h60
  text ".Layer_Name" at -604.1,-2728.57 h60
M11 Gerber Information:
  lines w10: -1473.1,-2800.25 5126.9,-2800.25 ; -1473.1,-2596.91 5128.9,-2596.91 ; -1473.1,-2393.58 -1473.1,-3003.58 2531.9,-3003.58 5128.9,-3003.58 5128.9,-2393.58 -1472.6,-2393.58 -1472.6,-3003.58 102.9,-3003.58 ; 991.9,-3003.58 991.9,-2393.58 ; 2258.9,-2596.91 2258.9,-2393.58 ; 3098.9,-2596.91 3098.9,-2393.58 ; 3720.9,-3010.08 3720.9,-2807.25
  text "ALL ARTWORK VIEWED FROM TOP SIDE" at -1409.6,-2525.75 h60
  text "BOARD #:" at 1066.9,-2525.75 h60
  text ".PRJ_Number" at 1612.4,-2525.75 h60
  text "REV:" at 2456.9,-2525.75 h60
  text ".PCB_Rev" at 2748.4,-2525.75 h60
  text "SVN REV:" at 3294.9,-2525.75 h60
  text ".VersionControl_RevNumber" at 3800.9,-2525.75 h60
  text "LAYER NAME =" at -1409.6,-2728.57 h60
  text "TID #:" at 1066.9,-2729.08 h60
  text ".TID" at 1612.4,-2729.08 h60
  text "PLOT NAME =" at -1409.6,-2934.41 h60
  text ".plot_File_Name" at -604.1,-2934.41 h60
  text "GENERATED    :" at 1068.9,-2934.41 h60
  text ".Print_Date" at 1938.4,-2934.41 h60
  text ".Print_Time" at 2667.4,-2934.41 h60
  text "TEXAS INSTRUMENTS" at 3931.9,-2934.41 h60
M12 Stackup:
  drawing of 191 lines, arcs and shapes, not listed
  text "Layer" at 8609.47,5959.92 h60
  text "Name" at 9019.39,5959.92 h60
  text "Material" at 9949.13,5959.92 h60
  text "Thickness" at 10808.9,5959.92 h60
  text "Constant" at 11458.73,5959.92 h60
  text "Board Layer Stack" at 12028.59,5959.92 h60
  text "1" at 8609.47,5839.92 h60
  text "Top Overlay" at 9019.39,5839.92 h60
  text "2" at 8609.47,5719.92 h60
  text "Top Solder" at 9019.39,5719.92 h60
  text "Solder Resist" at 9949.13,5719.92 h60
  text "0.40mil" at 10808.9,5719.92 h60
  text "3.5" at 11458.73,5719.92 h60
  text "3" at 8609.47,5599.92 h60
  text "Top Layer" at 9019.39,5599.92 h60
  text "Copper" at 9949.13,5599.92 h60
  text "1.40mil" at 10808.9,5599.92 h60
  text "4" at 8609.47,5479.92 h60
  text "Dielectric1" at 9019.39,5479.92 h60
  text "FR-4" at 9949.13,5479.92 h60
  text "59.20mil" at 10808.9,5479.92 h60
  text "4.8" at 11458.73,5479.92 h60
  text "5" at 8609.47,5359.92 h60
  text "Bottom Layer" at 9019.39,5359.92 h60
  text "Copper" at 9949.13,5359.92 h60
  text "1.40mil" at 10808.9,5359.92 h60
  text "6" at 8609.47,5239.92 h60
  text "Bottom Solder" at 9019.39,5239.92 h60
  text "Solder Resist" at 9949.13,5239.92 h60
  text "0.40mil" at 10808.9,5239.92 h60
  text "3.5" at 11458.73,5239.92 h60
  text "7" at 8609.47,5119.92 h60
  text "Bottom Overlay" at 9019.39,5119.92 h60
  text ".Layer_Name" at -604.1,-2728.57 h60
M13 Component Bodies Top:
  text ".Layer_Name" at -604.1,-2728.57 h60
M14 Component Bodies Bottom:
  text ".Layer_Name" at -604.1,-2728.57 h60
M15 Courtyards Top:
  text ".Layer_Name" at -604.1,-2728.57 h60
M16 Courtyards Bottom:
  text ".Layer_Name" at -604.1,-2728.57 h60
Drill Drawing:
  lines w10: 4345.59,1211.96 4367.69,1223.01 4389.79,1211.96 4378.74,1234.06 4389.79,1256.16 4367.69,1245.11 4345.59,1256.16 4356.64,1234.06 4345.59,1211.96 ; 4345.59,1322.46 4356.64,1322.46 4367.69,1311.41 4378.74,1322.46 4389.79,1322.46 4378.74,1333.51 4389.79,1344.56 4378.74,1344.56 4367.69,1355.61 4356.64,1344.56 4345.59,1344.56 4356.64,1333.51 4345.59,1322.46 ; 4345.59,1421.91 4356.64,1421.91 4356.64,1410.86 4378.74,1410.86 4378.74,1421.91 4389.79,1421.91 4389.79,1444.01 4378.74,1444.01 4378.74,1455.06 4356.64,1455.06 4356.64,1444.01 4345.59,1444.01 4345.59,1421.91
  lines w12: 4304.9,1182.12 6194.26,1182.12 ; 4304.9,1480.47 6194.26,1480.47 ; 4620.56,1082.67 4620.56,1579.92 ; 4937.67,1082.67 4937.67,1579.92 ; 5559.67,1082.67 5559.67,1579.92 ; 5804.01,1082.67 5804.01,1579.92 ; 4304.9,1082.67 6194.26,1082.67 6194.26,1579.92 4304.9,1579.92 4304.9,1082.67
  text "Symbol" at 4364.57,1510.31 h72
  text "Quantity" at 4650.39,1510.31 h72
  text "Finished Hole Size" at 4967.5,1510.31 h72
  text "Plated" at 5589.5,1510.31 h72
  text "Hole Type" at 5833.85,1510.31 h72
  text "4" at 4650.39,1410.86 h60
  text "7.87mil (0.200mm)" at 4967.5,1410.86 h60
  text "PTH" at 5589.5,1410.86 h60
  text "Round" at 5833.85,1410.86 h60
  text "9" at 4650.39,1311.41 h60
  text "29.53mil (0.750mm)" at 4967.5,1311.41 h60
  text "PTH" at 5589.5,1311.41 h60
  text "Round" at 5833.85,1311.41 h60
  text "7" at 4650.39,1211.96 h60
  text "61.81mil (1.570mm)" at 4967.5,1211.96 h60
  text "PTH" at 5589.5,1211.96 h60
  text "Round" at 5833.85,1211.96 h60
  text "20 Total" at 4650.39,1112.51 h60
  text ".Layer_Name" at -604.1,-2728.57 h60

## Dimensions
-1181.1,-2270.08 to -181.1,-2270.08 on M2 Board Dimensions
